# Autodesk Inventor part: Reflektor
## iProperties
Created: 2005-01
Part Number: Reflektor
Document SubType Name: Sheet Metal
Designer: KK
Manufacturer: Standard
Standards Organization: Custom
Description: REF-SIMI Ø150
Author: KK
Title: REF-SIMI Ø150
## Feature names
1. Ausschneiden1
